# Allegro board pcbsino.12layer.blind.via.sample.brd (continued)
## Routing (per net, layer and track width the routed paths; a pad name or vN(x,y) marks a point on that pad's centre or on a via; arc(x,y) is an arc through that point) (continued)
DDR1_D9: length 19.7
  TOP w0.114: U6.AF27 19.85,38.39 19.19,38.39 18.44,37.63 18,37.63 17.82,37.81 17.82,38.09 17.97,38.24 v2(18.48,38.24) ; v2(15.51,41.36) 15.64,41.24 16.53,41.24 16.78,41.49 16.78,42.41 16.88,42.51 17.04,42.51 17.14,42.61 17.14,42.75 17.04,42.85 16.88,42.85 16.78,42.95 16.78,43.09 16.88,43.19 17.04,43.19 17.14,43.29 17.14,43.44 17.04,43.54 16.88,43.54 16.78,43.64 16.78,44.1 16.67,44.21 U8.A7
  INT_L3 w0.091: v2(15.51,41.36) 15.51,43.33 15.6,43.42 15.83,43.42 15.92,43.33 15.92,40.86 17.6,39.17 17.6,39.06 17.44,38.89 17.44,38.78 17.52,38.7 17.63,38.7 17.8,38.86 17.91,38.86 17.99,38.78 17.99,38.67 17.82,38.51 17.82,38.39 17.9,38.31 18.02,38.31 18.18,38.47 18.3,38.47 18.48,38.29 v2(18.48,38.24)
DDR1_D10: length 19.7
  TOP w0.114: v2(13.86,47.82) 14.25,48.21 U8.C2 ; U6.AG27 20.26,38.77 v2(19.93,39.1)
  INT_L3 w0.091: v2(13.86,47.82) 13.83,47.79 13.83,47.48 13.93,47.38 14.08,47.38 14.16,47.46 14.16,48.17 14.24,48.25 14.39,48.25 14.47,48.17 14.47,47.46 14.55,47.38 14.72,47.38 14.8,47.46 14.8,48.73 14.88,48.81 15.05,48.81 15.13,48.73 15.13,47.46 15.21,47.38 15.91,47.38 15.99,47.46 15.99,48.14 16.07,48.22 16.18,48.22 16.26,48.14 16.26,47.46 16.34,47.38 16.81,47.38 17.74,46.45 17.74,41.41 17.75,41.41 17.75,41.4 19.93,39.21 v2(19.93,39.1)
DDR1_D11: length 19.7
  TOP w0.114: v2(15.54,43.83) 15.13,43.42 U8.B8 ; U6.AF28 19.31,37.97 18.61,37.27 17.59,37.27 17.09,37.78 17.09,38.33 17.19,38.43 17.7,38.43 17.8,38.53 17.8,38.67 17.7,38.77 17.19,38.77 17.09,38.87 v2(17.09,39.21)
  INT_L3 w0.091: v2(17.09,39.21) 16.98,39.31 16.67,39.31 16.52,39.46 16.52,39.57 16.62,39.68 16.62,39.79 16.54,39.87 16.43,39.87 16.32,39.77 16.21,39.77 16.13,39.85 16.13,39.96 16.23,40.07 16.23,40.18 16.15,40.26 16.04,40.26 15.93,40.16 15.82,40.16 15.74,40.24 15.74,40.35 15.84,40.45 15.84,40.57 15.76,40.65 15.65,40.65 15.55,40.54 15.43,40.54 15.35,40.62 15.35,40.74 15.46,40.84 15.46,40.96 15.38,41.04 15.26,41.04 15.16,40.93 15.04,40.93 14.96,41.01 14.96,41.13 15.07,41.23 15.07,41.34 14.99,41.42 14.87,41.42 14.77,41.32 14.66,41.32 14.58,41.4 14.58,41.51 14.68,41.62 14.68,41.73 14.6,41.81 14.49,41.81 14.38,41.71 14.27,41.71 14.11,41.86 14.11,42.01 14.3,42.19 15.11,42.19 15.21,42.29 15.21,42.42 15.11,42.51 14.21,42.51 14.11,42.6 14.11,42.77 14.19,42.85 15.13,42.85 15.21,42.93 15.21,43.04 15.13,43.12 14.19,43.12 14.11,43.2 14.11,43.35 14.22,43.45 15.16,43.45 v2(15.54,43.83)
DDR1_D12: length 19.7
  TOP w0.114: U6.AE26 20.74,37.5 v2(20.74,37.53) ; v2(13.73,46.7) 13.73,46.81 U8.C3
  INT_L3 w0.091: v2(20.74,37.53) 20.74,37.63 19.55,38.82 19.55,39.23 17.44,41.34 17.44,46.01 16.91,46.55 16.67,46.55 16.59,46.63 16.59,47 16.51,47.08 16.4,47.08 16.32,47 16.32,46.63 16.24,46.55 16.12,46.55 16.04,46.63 16.04,47 15.96,47.08 15.85,47.08 15.77,47 15.77,46.63 15.69,46.55 15.57,46.55 15.49,46.63 15.49,47 15.41,47.08 15.3,47.08 15.22,47 15.22,46.63 15.14,46.55 15.02,46.55 14.94,46.63 14.94,47 14.86,47.08 14.75,47.08 14.67,47 14.67,46.63 14.59,46.55 14.48,46.55 14.4,46.63 14.4,47 14.31,47.08 14.2,47.08 14.12,47 14.12,46.63 14.04,46.55 13.82,46.55 13.73,46.64 v2(13.73,46.7)
DDR1_D13: length 19.7
  TOP w0.114: U6.AC25 21.87,35.65 v2(21.53,35.98) ; v2(13.07,45.89) 12.3,45.89 12.18,45.77 12.18,44.88 12.3,44.77 13.41,44.77 13.53,44.65 U8.D7
  INT_L3 w0.091: v2(21.53,35.98) 21.53,36.06 20.93,36.67 19.45,36.67 19.12,37 18.33,37 16.76,38.57 16.37,38.57 13.5,41.44 13.5,43.24 13,43.75 13,44.12 13.08,44.2 13.12,44.2 13.2,44.28 13.2,44.39 13.12,44.47 13.08,44.47 13,44.55 13,44.66 13.08,44.75 13.12,44.75 13.2,44.83 13.2,44.94 13.12,45.02 13.08,45.02 13,45.1 13,45.81 v2(13.07,45.89)
DDR1_D14: length 19.7
  TOP w0.114: U8.C8 13.92,43.82 13.92,44.93 14.04,45.05 14.57,45.05 14.65,45.13 14.65,45.57 14.53,45.68 13.66,45.68 v2(13.4,45.43) ; U6.AC24 22.67,35.68 v2(22.29,36.06)
  INT_L3 w0.091: v2(22.29,36.06) 21.91,36.06 21,36.97 19.55,36.97 19.09,37.43 18.38,37.43 16.91,38.9 16.53,38.9 13.81,41.62 13.81,43.5 13.48,43.83 13.48,45.35 v2(13.4,45.43)
DDR1_D15: length 19.7
  TOP w0.114: v2(22.24,36.77) 21.87,36.39 U6.AD25 ; U8.A3 v2(16.7,48.18)
  INT_L3 w0.091: v2(22.24,36.77) 22.24,36.92 21.81,37.35 21.45,37.35 21.33,37.47 21.33,37.59 21.44,37.69 21.44,37.8 21.36,37.88 21.24,37.88 21.14,37.78 21.03,37.78 20.8,38.01 20.8,38.12 20.9,38.23 20.9,38.34 20.82,38.42 20.7,38.42 20.6,38.32 20.49,38.32 20.39,38.42 20.39,39.13 18,41.52 18,41.79 18.08,41.87 18.48,41.87 18.56,41.95 18.56,42.06 18.48,42.14 18.08,42.14 18,42.22 18,42.48 18.08,42.56 18.12,42.56 18.2,42.64 18.2,42.76 18.12,42.84 18.08,42.84 18,42.92 18,43.03 18.08,43.11 18.12,43.11 18.2,43.19 18.2,43.31 18.12,43.39 18.08,43.39 18,43.47 18,43.58 18.08,43.66 18.12,43.66 18.2,43.74 18.2,43.86 18.12,43.94 18.08,43.94 18,44.02 18,44.13 18.08,44.21 18.12,44.21 18.2,44.29 18.2,44.4 18.12,44.48 18.08,44.48 18,44.56 18,44.68 18.08,44.76 18.12,44.76 18.2,44.84 18.2,44.95 18.12,45.03 18.08,45.03 18,45.11 18,45.23 18.08,45.31 18.12,45.31 18.2,45.39 18.2,45.5 18.12,45.58 18.08,45.58 18,45.66 18,45.78 18.08,45.86 18.12,45.86 18.2,45.94 18.2,46.05 18.12,46.13 18.08,46.13 18,46.21 18,46.32 18.08,46.4 18.12,46.4 18.2,46.48 18.2,46.6 18.12,46.68 18.08,46.68 18,46.76 18,46.98 17.63,47.35 17.52,47.35 17.45,47.28 17.34,47.28 17.26,47.36 17.26,47.48 17.32,47.54 17.32,47.66 17.24,47.74 17.13,47.74 17.06,47.67 16.95,47.67 16.87,47.75 16.87,47.87 16.93,47.93 16.93,48.04 16.8,48.18 v2(16.7,48.18)
DDR1_D16: length 17.4
  TOP w0.114: v8(12.33,31.81) 11.93,32.21 U9.F8
  TOP w0.12: v8(25.47,31.97) U6.V20
  SIG_L5 w0.091: v8(12.33,31.81) 12.33,31.72 12.64,31.41 14.31,31.41 14.39,31.49 14.39,31.86 14.47,31.94 14.58,31.94 14.66,31.86 14.66,31.49 14.74,31.41 14.85,31.41 14.93,31.49 14.93,31.86 15.01,31.94 15.13,31.94 15.21,31.86 15.21,31.49 15.29,31.41 15.4,31.41 15.48,31.49 15.48,31.86 15.56,31.94 15.68,31.94 15.76,31.86 15.76,31.49 15.84,31.41 16.88,31.41 17.06,31.59 25.21,31.59 25.47,31.84 v8(25.47,31.97)
DDR1_D17: length 17.4
  TOP w0.12: U9.H8 v8(10.73,31.81) ; v8(25.47,32.77) U6.W20
  SIG_L5 w0.091: v8(25.47,32.77) 25.07,32.37 23.93,32.37 23.84,32.29 23.84,32.18 23.76,32.09 23.12,32.09 22.99,32.22 22.83,32.22 22.7,32.09 22.53,32.09 22.41,32.22 22.24,32.22 22.11,32.09 21.94,32.09 21.82,32.22 21.65,32.22 21.52,32.09 21.35,32.09 21.23,32.22 21.06,32.22 20.93,32.09 20.76,32.09 20.64,32.22 20.47,32.22 20.34,32.09 20.18,32.09 20.05,32.22 19.88,32.22 19.75,32.09 18.99,32.09 18.41,32.68 13.12,32.68 12.67,32.22 11.14,32.22 v8(10.73,31.81)
DDR1_D18: length 17.5
  TOP w0.114: v8(12.88,35.72) 12.89,35.73 12.89,36.04 U9.E3 ; U6.AB28 18.09,34.77 17.64,35.22 17.64,35.67 v8(17.62,35.7)
  SIG_L5 w0.091: v8(17.62,35.7) 17.62,36.67 17.53,36.75 17.05,36.75 16.96,36.84 16.96,36.96 17.05,37.05 17.53,37.05 17.62,37.13 17.62,37.96 17.49,38.09 17.18,38.09 17.09,38 17.09,37.66 16.73,37.3 16.11,37.3 15.66,36.86 15.66,36.84 14.87,36.84 14.69,37.03 14.69,37.44 14.6,37.53 14.48,37.53 14.39,37.44 14.39,37.03 14.31,36.94 13.99,36.94 13.9,36.86 13.9,36.68 13.82,36.59 13.7,36.59 13.61,36.68 13.61,36.86 13.52,36.94 13.23,36.94 12.82,36.54 11.32,36.54 11.24,36.46 11.24,36.2 11.34,36.11 12.59,36.11 12.88,35.82 v8(12.88,35.72)
DDR1_D19: length 17.5
  TOP w0.114: U9.F2 11.93,37.01 v8(12.33,37.41)
  TOP w0.12: U6.AC28 18.99,35.57 v8(18.88,35.69)
  SIG_L5 w0.091: v8(12.33,37.41) 11.93,37.81 10.17,37.81 10.02,37.95 10.02,38.62 10.2,38.8 17.77,38.8 18.88,37.69 18.88,37.09 18.96,37.01 19.31,37.01 19.4,36.92 19.4,36.8 19.31,36.71 18.96,36.71 18.88,36.63 18.88,36.5 18.96,36.42 19.31,36.42 19.4,36.33 19.4,36.21 19.31,36.12 18.96,36.12 18.88,36.04 v8(18.88,35.69)
DDR1_D20: length 17.4
  TOP w0.12: v8(10.73,36.61) 10.33,36.21 U9.H3 ; v8(19.87,35.97) U6.AC27
  SIG_L5 w0.091: v8(10.73,36.61) 10.28,36.16 9.54,36.16 9.21,35.83 9.21,34.07 9.69,33.59 11.37,33.59 12.11,34.33 19.45,34.33 20.06,34.94 20.06,35.78 v8(19.87,35.97)
DDR1_D21: length 17.4
  TOP w0.114: v8(10.73,32.61) U9.H7
  TOP w0.12: v8(26.27,33.57) U6.Y19
  SIG_L5 w0.091: v8(10.73,32.61) 11.18,33.06 12.18,33.06 12.67,33.54 20.31,33.54 20.77,34 25.62,34 25.63,34 25.84,34 v8(26.27,33.57)
DDR1_D22: length 17.5
  TOP w0.114: v8(11.53,37.41) 11.13,37.01 U9.G2
  TOP w0.12: v8(18.23,35.7) 18.23,35.29 18.35,35.17 19.87,35.17 U6.AB27
  SIG_L5 w0.091: v8(11.53,37.41) 11.45,37.33 11.45,37.03 11.54,36.94 12.61,36.94 12.75,37.08 12.75,37.69 12.89,37.83 13.73,37.83 13.82,37.92 13.82,38.36 13.9,38.44 14.03,38.44 14.11,38.36 14.11,37.92 14.2,37.83 15.69,37.83 16.32,38.47 17.67,38.47 18.08,38.06 18.08,37.85 18.19,37.75 18.39,37.75 18.56,37.58 18.56,37.18 18.47,37.09 18.01,37.09 17.92,37 17.92,36.88 18.01,36.8 18.47,36.8 18.56,36.71 18.56,36.59 18.47,36.5 18.01,36.5 17.92,36.41 17.92,36.29 18.01,36.21 18.47,36.21 18.56,36.12 18.56,35.93 18.33,35.7 v8(18.23,35.7)
DDR1_D23: length 17.4
  TOP w0.114: v8(12.33,32.61) U9.F7
  TOP w0.12: U6.Y20 v8(25.47,33.57)
  SIG_L5 w0.091: v8(25.47,33.57) 25.47,33.41 25.24,33.19 24.99,33.19 24.9,33.28 24.9,33.42 24.8,33.52 24.62,33.52 24.53,33.42 24.53,33.28 24.44,33.19 24.26,33.19 24.16,33.28 24.16,33.42 24.07,33.52 23.89,33.52 23.8,33.42 23.8,33.28 23.71,33.19 23.52,33.19 23.43,33.28 23.43,33.42 23.34,33.52 23.16,33.52 23.07,33.42 23.07,33.28 22.98,33.19 22.79,33.19 22.7,33.28 22.7,33.42 22.61,33.52 22.43,33.52 22.34,33.42 22.34,33.28 22.24,33.19 22.06,33.19 21.97,33.28 21.97,33.42 21.88,33.52 21.7,33.52 21.6,33.42 21.6,33.28 21.51,33.19 21.33,33.19 21.24,33.28 21.24,33.42 21.15,33.52 20.96,33.52 20.87,33.42 20.87,33.28 20.78,33.19 12.91,33.19 v8(12.33,32.61)
DDR1_D24: length 10.3
  TOP w0.114: U9.A2 16.34,37.01 16.47,37.14 v2(16.48,37.14)
  TOP w0.12: v2(23.83,34.34) U6.AA23
  INT_L3 w0.091: v2(16.48,37.14) 17.07,37.14 17.18,37.02 17.18,36.9 17.01,36.73 17.01,36.61 17.1,36.52 17.22,36.52 17.39,36.69 17.51,36.69 18.03,36.18 18.97,36.18 19.55,35.6 19.71,35.6 19.71,35.6 20.69,35.6 21.12,35.17 21.73,35.17 22.14,34.76 23.49,34.76 23.83,34.41 v2(23.83,34.34)
DDR1_D25: length 10.3
  TOP w0.114: v2(15.39,31.83) 15.33,31.89 15.13,32.19 U9.B8
  TOP w0.12: v2(23.87,32.78) U6.Y22
  INT_L3 w0.091: v2(15.39,31.83) 15.75,31.83 16.12,32.19 16.53,32.19 16.88,31.84 23.16,31.84 23.87,32.55 v2(23.87,32.78)
DDR1_D26: length 10.3
  TOP w0.114: U9.C8 v2(14.67,31.86)
  TOP w0.12: v2(23.14,32.85) U6.Y23
  INT_L3 w0.091: v2(23.14,32.85) 22.39,32.1 18.63,32.1 18.03,32.7 16.17,32.7 15.66,32.19 15,32.19 v2(14.67,31.86)
DDR1_D27: length 10.3
  TOP w0.114: U9.A3 15.52,36.61 v2(15.51,36.61)
  TOP w0.12: U6.AA24 23,34.3 v2(23.05,34.3)
  INT_L3 w0.091: v2(15.51,36.61) 15.59,36.69 15.88,36.69 16.07,36.5 16.07,35.5 16.27,35.29 20.56,35.29 20.97,34.89 21.61,34.89 22.01,34.48 22.96,34.48 23.05,34.39 v2(23.05,34.3)
DDR1_D28: length 10.3
  TOP w0.114: U9.A7 15.91,33.01 v2(15.53,32.63)
  TOP w0.12: U6.Y24 22.99,33.49 v2(23,33.49)
  INT_L3 w0.091: v2(15.53,32.63) 15.49,32.67 15.49,32.89 15.58,32.98 18.28,32.98 18.91,32.35 20.82,32.35 20.95,32.48 20.95,33.16 21.23,33.44 21.65,33.44 21.73,33.35 21.73,33.27 21.82,33.19 21.94,33.19 22.03,33.27 22.03,33.35 22.11,33.44 22.95,33.44 v2(23,33.49)
DDR1_D29: length 10.3
  TOP w0.114: U9.C2 v2(14.69,37.36)
  TOP w0.12: U6.AA26 21.02,33.97 v2(20.6,34.39)
  INT_L3 w0.091: v2(14.69,37.36) 14.14,36.82 14.14,36.63 14.23,36.54 14.36,36.54 14.44,36.45 14.44,36.33 14.36,36.24 14.28,36.24 14.19,36.16 14.19,35.75 15.21,34.73 20.26,34.73 v2(20.6,34.39)
DDR1_D30: length 10.3
  TOP w0.114: U9.C3 14.71,36.59 v2(14.75,36.59)
  TOP w0.12: v2(21.53,34.31) U6.AA25
  INT_L3 w0.091: v2(21.53,34.31) 21.31,34.53 20.96,34.53 20.48,35.01 15.99,35.01 15.83,35.17 15.69,35.17 15.54,35.01 15.33,35.01 15.19,35.16 15.19,35.28 15.2,35.3 15.2,35.42 15.12,35.51 15,35.51 14.98,35.49 14.86,35.49 14.75,35.6 14.75,35.87 14.84,35.96 15.07,35.96 15.16,36.05 15.16,36.17 15.07,36.25 14.84,36.25 14.75,36.34 v2(14.75,36.59)
DDR1_D31: length 10.3
  TOP w0.114: U6.AA28 19.37,34.07 v2(19.04,34.07) ; U9.D7 13.53,32.93 v2(13.17,32.58)
  INT_L3 w0.091: v2(13.17,32.58) 12.69,33.06 12.69,34.79 12.95,35.04 13.68,35.04 14.57,34.15 18.81,34.15 18.89,34.07 v2(19.04,34.07)
DDR1_DQM0: length 20.9
  TOP w0.114: v8(12.33,43.81) U8.E7
  TOP w0.12: v8(23.07,36.77) U6.AD23
  SIG_L5 w0.091: v8(12.33,43.81) 11.93,43.41 11.93,41.97 12.34,41.57 13.46,41.57 13.55,41.66 13.55,41.93 13.64,42.02 13.82,42.02 13.91,41.93 13.91,41.66 14,41.57 14.19,41.57 14.28,41.66 14.28,42.06 14.41,42.19 15.5,42.19 16.12,41.57 16.79,41.57 16.88,41.66 16.88,42.62 16.98,42.71 17.16,42.71 17.25,42.62 17.25,41.66 17.34,41.57 17.64,41.57 18.33,40.88 18.89,40.88 21.05,38.72 21.7,38.72 21.78,38.8 22.11,38.8 22.11,38.8 22.47,38.8 22.7,38.57 22.7,37.74 22.69,37.73 22.69,37.15 v8(23.07,36.77)
DDR1_DQM1: length 19.7
  TOP w0.114: U8.D3 13.53,47.18 v2(13.02,46.67) ; U6.AB23 v2(23.06,35.18)
  INT_L3 w0.091: v2(13.02,46.67) 12.72,46.37 12.72,41.82 16.3,38.24 16.65,38.24 18.31,36.59 19.07,36.59 19.24,36.41 20.82,36.41 21.12,36.11 21.12,35.9 21.43,35.6 22.64,35.6 v2(23.06,35.18)
DDR1_DQM2: length 17.4
  TOP w0.114: U9.E7 12.18,33.55 v8(12.18,33.77)
  TOP w0.12: v8(20.67,35.97) U6.AC26
  SIG_L5 w0.091: v8(20.67,35.97) 20.75,36.06 21.74,36.06 21.84,35.96 21.84,35.82 21.75,35.74 21.16,35.74 21.07,35.65 21.07,35.53 21.16,35.44 21.75,35.44 21.84,35.35 21.84,35.23 21.75,35.15 20.86,35.15 20.77,35.06 20.77,34.94 20.86,34.85 21.75,34.85 21.84,34.77 21.84,34.53 21.68,34.38 20.51,34.38 19.98,33.85 12.34,33.85 12.26,33.77 v8(12.18,33.77)
DDR1_DQM3: length 10.3
  TOP w0.114: U9.D3 13.17,36.56 v2(13.12,36.56)
  TOP w0.12: v2(19.99,34.26) U6.AA27
  INT_L3 w0.091: v2(19.99,34.26) 19.81,34.43 14.7,34.43 14.4,34.73 14.4,34.85 14.5,34.95 14.5,35.07 14.42,35.16 14.3,35.16 14.19,35.06 14.07,35.06 13.98,35.14 13.98,35.27 14.09,35.37 14.09,35.49 14,35.58 13.88,35.58 13.78,35.47 13.65,35.47 13.5,35.62 13.5,36.6 13.41,36.69 13.25,36.69 v2(13.12,36.56)
DDR1_DQS0_N: length 21
  TOP w0.102: v8(11.53,47.81) 11.49,47.81 11.13,47.45 U8.G3 ; U6.AG25 21.55,39.09 21.55,39.13 v8(21.49,39.18)
  SIG_L5 w0.089: v8(11.53,47.81) 11.78,47.56 11.78,46.33 12.24,45.87 12.84,45.87 12.93,45.78 12.93,45.56 13.16,45.33 13.54,45.33 13.77,45.56 13.77,45.78 13.86,45.87 14.03,45.87 14.12,45.78 14.12,45.56 14.35,45.33 14.73,45.33 14.96,45.56 14.96,45.78 15.05,45.87 15.23,45.87 15.32,45.78 15.32,45.56 15.55,45.33 15.92,45.33 16.15,45.56 16.15,45.78 16.24,45.87 16.42,45.87 16.51,45.78 16.51,45.56 16.74,45.33 17.12,45.33 17.35,45.56 17.35,45.78 17.44,45.87 18.37,45.87 21.33,42.91 21.33,40.91 20.74,40.32 20.74,39.74 21.12,39.36 21.4,39.36 21.49,39.27 v8(21.49,39.18)
DDR1_DQS0_P: length 21
  TOP w0.102: U8.F3 11.93,47.46 12.26,47.79 12.31,47.79 v8(12.33,47.81) ; v8(21.49,39.98) 21.5,39.97 21.5,39.94 U6.AH25
  SIG_L5 w0.089: v8(12.33,47.81) 12.29,47.81 12.29,47.82 12.11,47.82 12.02,47.73 12.02,46.43 12.34,46.11 12.94,46.11 13.17,45.88 13.17,45.66 13.26,45.57 13.44,45.57 13.53,45.66 13.53,45.88 13.76,46.11 14.13,46.11 14.36,45.88 14.36,45.66 14.45,45.57 14.63,45.57 14.72,45.66 14.72,45.88 14.95,46.11 15.33,46.11 15.56,45.88 15.56,45.66 15.65,45.57 15.82,45.57 15.91,45.66 15.91,45.88 16.14,46.11 16.52,46.11 16.75,45.88 16.75,45.66 16.84,45.57 17.02,45.57 17.11,45.66 17.11,45.88 17.34,46.11 18.47,46.11 21.57,43.01 21.57,40.81 20.98,40.22 20.98,39.84 21.22,39.6 21.39,39.6 21.51,39.71 21.51,39.97 v8(21.49,39.98)
DDR1_DQS1_N: length 19.8
  TOP w0.102: U6.AE28 19.47,37.32 19.63,37.48 v2(19.63,37.53) ; v2(14.7,43.75) 15.13,44.18 U8.B7
  INT_L3 w0.089: v2(14.7,43.75) 14.91,43.97 14.91,44.66 14.68,44.89 14.16,44.89 14.08,44.98 14.08,45.8 14.24,45.96 15.03,45.96 15.31,45.68 15.31,44.87 15.53,44.65 15.9,44.65 16.15,44.89 16.15,45.65 16.23,45.74 16.62,45.74 16.74,45.57 16.74,44.51 16.66,44.44 16.52,44.44 16.3,44.22 16.3,43.91 16.52,43.69 16.66,43.69 16.74,43.61 16.74,41.84 16.66,41.76 16.49,41.76 16.27,41.54 16.27,41.23 16.49,41.01 16.66,41.01 16.74,40.93 16.74,40.55 17.17,40.13 17.48,40.13 17.65,40.3 17.76,40.3 17.83,40.22 17.83,40.11 17.66,39.94 17.66,39.63 18.74,38.56 18.87,38.56 19.65,37.78 19.65,37.55 v2(19.63,37.53)
DDR1_DQS1_P: length 19.7
  TOP w0.102: U8.C7 14.37,44.17 v2(14.4,44.17) ; v2(20.19,37.53) 20.27,37.46 U6.AE27
  INT_L3 w0.089: v2(14.4,44.17) 14.67,44.44 14.67,44.56 14.58,44.65 14.06,44.65 13.83,44.88 13.83,45.9 14.14,46.2 15.13,46.2 15.55,45.78 15.55,44.97 15.63,44.89 15.8,44.89 15.9,44.99 15.9,45.75 16.14,45.98 16.75,45.98 16.98,45.65 16.98,44.41 16.76,44.19 16.62,44.19 16.54,44.12 16.54,44.01 16.62,43.93 16.76,43.93 16.98,43.71 16.98,41.74 16.76,41.52 16.59,41.52 16.51,41.44 16.51,41.33 16.59,41.25 16.76,41.25 16.98,41.03 16.98,40.65 17.26,40.37 17.38,40.37 17.55,40.54 17.86,40.54 18.08,40.32 18.08,40.01 17.91,39.84 17.91,39.73 18.84,38.8 18.97,38.8 20.12,37.64 20.12,37.6 v2(20.19,37.53)
DDR1_DQS2_N: length 17.5
  TOP w0.102: v8(11.09,35.6) 11.29,35.8 11.29,36.04 U9.G3 ; v8(16.88,35.67) 16.88,35.88 17.52,36.51 19.33,36.51 U6.AD28
  SIG_L5 w0.089: v8(16.88,35.67) 16.74,35.81 16.07,35.81 15.74,36.15 15.41,36.15 15.19,35.93 15.19,35.15 14.91,34.87 14.33,34.87 14.11,35.1 14.11,35.76 14.02,35.84 13.9,35.84 13.82,35.76 13.82,35.1 13.59,34.87 12.17,34.87 11.45,34.15 9.9,34.15 9.67,34.38 9.67,35.14 9.9,35.37 10.58,35.37 10.82,35.13 11.17,35.13 11.37,35.33 11.37,35.47 11.24,35.6 v8(11.09,35.6)
DDR1_DQS2_P: length 17.5
  TOP w0.102: v8(11.73,35.6) 11.73,36.01 U9.F3 ; U6.AD27 19.87,36.77 17.37,36.77 16.81,36.21 v8(16.6,36.21)
  SIG_L5 w0.089: v8(16.6,36.21) 16.5,36.11 16.12,36.11 15.84,36.39 15.31,36.39 14.95,36.03 14.95,35.25 14.81,35.12 14.43,35.12 14.35,35.2 14.35,35.86 14.12,36.09 13.8,36.09 13.57,35.86 13.57,35.2 13.49,35.12 12.07,35.12 11.35,34.39 10,34.39 9.91,34.48 9.91,35.04 10,35.13 10.48,35.13 10.72,34.89 11.27,34.89 11.61,35.23 11.61,35.48 v8(11.73,35.6)
DDR1_DQS3_N: length 10.3
  TOP w0.102: v2(20.54,33.46) 20.54,33.46 20.27,33.19 U6.Y27 ; v2(14.77,32.68) 14.78,32.68 14.8,32.68 U9.B7
  INT_L3 w0.089: v2(20.54,33.46) 20.3,33.22 18.72,33.22 18.42,33.52 14.36,33.52 13.94,33.93 13.63,33.93 13.49,33.8 13.49,33.51 13.83,33.17 14.29,33.17 14.77,32.69 v2(14.77,32.68)
DDR1_DQS3_P: length 10.4
  TOP w0.102: U6.Y28 19.54,33.17 v2(19.88,33.52) ; v2(14,32.61) 14.06,32.61 14.33,32.96 U9.C7
  INT_L3 w0.089: v2(14,32.61) 14.17,32.61 14.28,32.72 14.28,32.84 14.19,32.93 13.73,32.93 13.25,33.41 13.25,33.9 13.53,34.18 14.04,34.18 14.46,33.76 18.52,33.76 18.82,33.46 19.82,33.46 v2(19.88,33.52)
DDR1_ODT0: length 54.7
  TOP w0.114: U8.K1 v8(9.14,49.42) ; U6.AE20 25.87,37.2 v8(25.49,37.58)
  TOP w0.12: U9.K1 v8(8.33,38.21)
  INT_L3 w0.094: v8(9.14,49.42) 8.73,49.01 8.73,47.11 9.87,45.96 9.87,41.01 8.33,39.46 v8(8.33,38.21)
  SIG_L8 w0.091: v8(9.14,49.42) 9.14,50.37 9.23,50.46 9.54,50.46 9.63,50.37 9.63,49.96 9.72,49.87 9.86,49.87 9.95,49.96 9.95,50.37 10.04,50.46 10.18,50.46 10.27,50.37 10.27,49.96 10.36,49.87 10.5,49.87 10.59,49.96 10.59,50.37 10.68,50.46 10.82,50.46 10.91,50.37 10.91,49.96 11,49.87 11.14,49.87 11.23,49.96 11.23,50.37 11.32,50.46 11.46,50.46 11.55,50.37 11.55,49.96 11.64,49.87 11.78,49.87 11.87,49.96 11.87,50.37 11.96,50.46 12.1,50.46 12.19,50.37 12.19,49.96 12.28,49.87 12.42,49.87 12.51,49.96 12.51,50.37 12.6,50.46 12.74,50.46 12.83,50.37 12.83,49.96 12.92,49.87 13.06,49.87 13.15,49.96 13.15,50.37 13.24,50.46 13.38,50.46 13.47,50.37 13.47,49.96 13.56,49.87 13.7,49.87 13.79,49.96 13.79,50.37 13.88,50.46 14.02,50.46 14.11,50.37 14.11,49.96 14.2,49.87 14.34,49.87 14.43,49.96 14.43,50.37 14.52,50.46 14.66,50.46 14.75,50.37 14.75,49.96 14.84,49.87 14.98,49.87 15.07,49.96 15.07,50.37 15.16,50.46 15.3,50.46 15.39,50.37 15.39,49.96 15.48,49.87 15.62,49.87 15.71,49.96 15.71,50.37 15.8,50.46 15.94,50.46 16.03,50.37 16.03,49.96 16.12,49.87 16.26,49.87 16.35,49.96 16.35,50.37 16.44,50.46 16.58,50.46 16.67,50.37 16.67,49.96 16.76,49.87 16.9,49.87 16.99,49.96 16.99,50.37 17.08,50.46 17.22,50.46 17.31,50.37 17.31,49.96 17.4,49.87 17.54,49.87 17.63,49.96 17.63,50.37 17.72,50.46 18.51,50.46 18.76,50.2 18.76,49.98 18.67,49.89 18.17,49.89 18.08,49.8 18.08,49.66 18.17,49.57 18.67,49.57 18.76,49.48 18.76,46.9 25.07,40.59 25.07,37.99 25.48,37.58 v8(25.49,37.58)
  BOTTOM w0.114: 8.33,38.81 8.48,38.96 R92.2
  BOTTOM w0.12: 8.33,38.81 v8(8.33,38.21)
DDR1_RASN: length 54.8
  TOP w0.12: v8(9.13,36.61) U9.J3 ; v8(26.27,37.57) U6.AF20 ; U8.J3 v8(9.13,47.81)
  INT_L3 w0.094: v8(9.13,36.61) 8.75,36.99 8.75,39.28 10.23,40.75 10.23,46.19 9.13,47.29 v8(9.13,47.81)
  SIG_L5 w0.091: v8(26.27,37.57) 25.9,37.94 25.9,39.07 25.81,39.16 24.92,39.16 24.83,39.26 24.83,39.39 24.92,39.48 25.81,39.48 25.9,39.58 25.9,39.71 25.81,39.8 24.92,39.8 24.83,39.9 24.83,40.03 24.92,40.12 25.81,40.12 25.9,40.22 25.9,40.35 25.81,40.44 24.92,40.44 24.83,40.54 24.83,40.67 24.92,40.76 25.81,40.76 25.9,40.86 25.9,40.99 25.81,41.08 24.92,41.08 24.83,41.18 24.83,41.31 24.92,41.4 25.81,41.4 25.9,41.5 25.9,41.63 25.81,41.72 24.92,41.72 24.83,41.82 24.83,41.95 24.92,42.04 25.81,42.04 25.9,42.14 25.9,43.45 21.31,48.04 20.21,48.04 19.77,48.48 19.77,48.61 19.99,48.82 19.99,48.95 19.89,49.05 19.76,49.05 19.55,48.84 19.42,48.84 19.32,48.93 19.32,49.06 19.53,49.28 19.53,49.41 19.44,49.5 19.31,49.5 19.09,49.29 18.97,49.29 18.87,49.39 18.87,49.52 19.08,49.73 19.08,49.86 18.98,49.96 18.86,49.96 18.64,49.74 18.51,49.74 18.28,49.97 8.96,49.97 8.73,49.75 8.73,48.21 v8(9.13,47.81)
  BOTTOM w0.114: R70.2 9.19,35.95 9.13,36.01
  BOTTOM w0.12: 9.13,36.01 v8(9.13,36.61)
DDR1_RST: length 55.7
  TOP w0.114: U6.AG21 v2(25.42,39.13)
  TOP w0.12: U8.T2 3.93,48.21 3.51,48.63 v8(2.94,48.63) ; U9.T2 3.93,37.01 v8(3.53,37.41)
  INT_L3 w0.091: v8(2.94,48.63) 2.94,51.19 4.49,52.74 17.92,52.74 21.28,49.39 21.28,45.33 27.47,39.13 27.47,38.11 27.35,37.99 26.15,37.99 25.9,38.24 25.9,38.65 25.58,38.96 ; 25.39,39.1 25.44,39.1 25.58,38.96 ; v2(25.42,39.13) 25.58,38.96
  SIG_L5 w0.091: v8(2.94,48.63) 2.3,47.99 2.3,38.77 2.48,38.6 2.48,38.46 v8(3.53,37.41)
  BOTTOM w0.114: v8(3.53,37.41) 3.53,38.7 R95.1
DDR1_WEN: length 54.7
  TOP w0.114: U8.L3 v2(7.52,47.82) ; U6.AH21 25.07,39.73 24.17,40.63 22.52,40.63 v2(22.17,40.98)
  TOP w0.12: v8(7.53,36.61) 7.93,36.21 U9.L3
  INT_L3 w0.091: v2(22.17,40.98) 22.17,41.26 21.77,41.66 21.64,41.66 21.42,41.43 21.29,41.43 21.19,41.53 21.19,41.66 21.42,41.88 21.42,42.01 21.32,42.11 21.19,42.11 20.96,41.88 20.84,41.88 20.74,41.98 20.74,42.11 20.96,42.33 20.96,42.46 20.87,42.56 20.74,42.56 20.51,42.33 20.38,42.33 20.29,42.43 20.29,42.56 20.51,42.79 20.51,42.92 20.42,43.01 20.29,43.01 20.06,42.79 19.93,42.79 19.83,42.88 19.83,43.01 20.06,43.24 20.06,43.37 19.96,43.47 19.83,43.47 19.61,43.24 19.48,43.24 19.38,43.34 19.38,43.47 19.61,43.69 19.61,43.82 19.33,44.1 19.33,48.78 17.75,50.36 17.36,50.36 17.27,50.26 17.27,50.02 17.18,49.92 17.04,49.92 16.95,50.02 16.95,50.26 16.86,50.36 16.72,50.36 16.63,50.26 16.63,50.02 16.54,49.92 16.4,49.92 16.31,50.02 16.31,50.26 16.22,50.36 16.08,50.36 15.99,50.26 15.99,50.02 15.9,49.92 15.76,49.92 15.67,50.02 15.67,50.26 15.58,50.36 15.44,50.36 15.35,50.26 15.35,50.02 15.26,49.92 15.12,49.92 15.03,50.02 15.03,50.26 14.94,50.36 14.8,50.36 14.71,50.26 14.71,50.02 14.62,49.92 14.48,49.92 14.39,50.02 14.39,50.26 14.3,50.36 14.16,50.36 14.07,50.26 14.07,50.02 13.98,49.92 13.84,49.92 13.75,50.02 13.75,50.26 13.66,50.36 13.52,50.36 13.43,50.26 13.43,50.02 13.34,49.92 13.2,49.92 13.11,50.02 13.11,50.26 13.02,50.36 12.88,50.36 12.79,50.26 12.79,50.02 12.7,49.92 12.56,49.92 12.47,50.02 12.47,50.26 12.38,50.36 12.24,50.36 12.15,50.26 12.15,50.02 12.06,49.92 11.92,49.92 11.83,50.02 11.83,50.26 11.74,50.36 11.6,50.36 11.51,50.26 11.51,50.02 11.42,49.92 11.28,49.92 11.19,50.02 11.19,50.26 11.1,50.36 10.96,50.36 10.87,50.26 10.87,50.02 10.78,49.92 10.64,49.92 10.55,50.02 10.55,50.26 10.46,50.36 10.32,50.36 10.23,50.26 10.23,50.02 10.14,49.92 10,49.92 9.91,50.02 9.91,50.26 9.82,50.36 9.68,50.36 9.59,50.26 9.59,50.02 9.5,49.92 9.36,49.92 9.27,50.02 9.27,50.26 9.18,50.36 9.04,50.36 8.95,50.26 8.95,50.02 8.86,49.92 8.72,49.92 8.63,50.02 8.63,50.26 8.54,50.36 8.02,50.36 7.92,50.25 7.92,48.22 v2(7.52,47.82)
  INT_L3 w0.094: v2(7.52,47.82) 7.52,46.74 8.73,45.53 8.73,41.19 7.13,39.59 7.13,37.01 v8(7.53,36.61)
  BOTTOM w0.114: 7.53,36.01 7.54,36 R72.2
  BOTTOM w0.12: 7.53,36.01 v8(7.53,36.61)
DDR2_A0: length 45
  TOP w0.114: v8(21.29,29.79) 21.87,29.22 U6.R25 ; U10.N3 6.23,13.91 ; v8(5.91,25.41) 5.93,25.41 U11.N3
  TOP w0.12: 6.23,13.91 v8(5.93,14.21)
  INT_L3 w0.094: v8(5.91,25.41) 5.53,25.03 5.53,14.61 v8(5.93,14.21)
  SIG_L8 w0.091: v8(5.91,25.41) 5.53,25.79 5.53,27.88 5.81,28.16 6.05,28.16 6.14,28.06 6.14,26.81 6.29,26.66 6.43,26.66 6.52,26.75 6.52,28.06 6.61,28.16 7.48,28.16 7.58,28.06 7.58,26.83 7.67,26.73 7.89,26.73 7.99,26.84 7.99,28.06 8.08,28.16 8.43,28.16 8.73,27.85 8.73,25.01 8.91,24.83 10.08,24.83 10.28,25.03 10.28,27.37 10.58,27.67 15.65,27.67 15.74,27.77 15.74,28.33 15.92,28.51 16.43,28.51 17.85,29.93 20.5,29.93 20.57,30.01 21.07,30.01 v8(21.29,29.79)
  BOTTOM w0.114: R106.2 6.04,14.1 v8(5.93,14.21)
DDR2_A1: length 44.9
  TOP w0.114: U11.P7 5.53,21.81 v8(5.13,21.41) ; U10.P7 5.53,10.61
  TOP w0.12: 5.53,10.61 v8(5.13,10.21) ; 5.53,21.81 v8(5.13,21.41) ; v8(20.67,29.57) U6.R26
  SIG_L5 w0.091: v8(20.67,29.57) 20.61,29.63 18.46,29.63 18.08,29.25 17.51,29.25 17.42,29.34 17.42,29.44 17.33,29.53 17.19,29.53 17.1,29.44 17.1,29.34 17.01,29.25 16.87,29.25 16.78,29.34 16.78,29.44 16.69,29.53 16.55,29.53 16.46,29.44 16.46,29.34 16.37,29.25 16.23,29.25 16.14,29.34 16.14,29.44 16.05,29.53 15.91,29.53 15.82,29.44 15.82,29.34 15.73,29.25 15.59,29.25 15.5,29.34 15.5,29.44 15.41,29.53 15.27,29.53 15.18,29.44 15.18,29.34 15.09,29.25 14.95,29.25 14.86,29.34 14.86,29.44 14.77,29.53 14.63,29.53 14.54,29.44 14.54,29.34 14.45,29.25 7.54,29.25 7.45,29.16 7.45,28.43 7.35,28.33 7.22,28.33 7.13,28.43 7.13,29.16 7.03,29.25 6.9,29.25 6.81,29.16 6.81,28.43 6.71,28.33 6.58,28.33 6.49,28.43 6.49,29.16 6.39,29.25 6.26,29.25 6.17,29.16 6.17,28.43 6.07,28.33 5.94,28.33 5.85,28.43 5.85,29.16 5.75,29.25 5.61,29.25 5.43,29.07 5.43,27.24 4.75,26.57 4.75,23.55 5.13,23.17 v8(5.13,21.41)
  SIG_L10 w0.094: v8(5.13,21.41) 4.73,21.01 4.73,13.81 5.18,13.36 5.18,10.26 v8(5.13,10.21)
  BOTTOM w0.12: R107.2 5.13,10.95 v8(5.13,10.21)
DDR2_A2: length 44.9
  TOP w0.114: U10.P3 5.53,13.81 ; v2(18.1,30.42) 18.1,29.73 18.66,29.17 U6.R28 ; 5.26,25.27 U11.P3 5.53,25.01
  TOP w0.12: 5.53,25.01 5.26,25.27 5.26,25.27 v2(5.12,25.41) ; 5.53,13.81 v8(5.13,14.21)
  INT_L3 w0.091: v2(18.1,30.42) 18.03,30.42 17.95,30.34 16.35,30.34 16.25,30.24 16.06,30.24 15.95,30.34 15.76,30.34 15.66,30.24 15.47,30.24 15.36,30.34 15.17,30.34 15.07,30.24 14.88,30.24 14.78,30.34 14.58,30.34 14.48,30.24 14.29,30.24 14.19,30.34 13.99,30.34 13.89,30.24 13.7,30.24 13.6,30.34 13.4,30.34 13.3,30.24 13.11,30.24 13.01,30.34 12.81,30.34 12.71,30.24 12.52,30.24 12.42,30.34 12.23,30.34 12.12,30.24 11.93,30.24 11.83,30.34 11.64,30.34 11.53,30.24 11.34,30.24 11.24,30.34 11.05,30.34 10.95,30.24 10.75,30.24 10.65,30.34 10.46,30.34 10.36,30.24 10.16,30.24 10.06,30.34 9.87,30.34 9.77,30.24 9.57,30.24 9.47,30.34 9.28,30.34 9.18,30.24 8.98,30.24 8.88,30.34 8.69,30.34 8.59,30.24 8.39,30.24 8.29,30.34 8.1,30.34 8,30.24 7.81,30.24 7.7,30.34 7.51,30.34 7.41,30.24 7.22,30.24 7.11,30.34 6.92,30.34 6.82,30.24 6.63,30.24 6.53,30.34 6.16,30.34 6.07,30.25 6.07,29.66 5.98,29.58 5.86,29.58 5.78,29.66 5.78,30.25 5.69,30.34 5.57,30.34 5.48,30.25 5.48,29.66 5.39,29.58 5.27,29.58 5.19,29.66 5.19,30.25 5.1,30.34 4.79,30.34 4.44,29.99 4.44,29.34 4.52,29.25 5.49,29.25 5.58,29.17 5.58,29.05 5.49,28.96 4.52,28.96 4.44,28.87 4.44,28.75 4.52,28.66 5.49,28.66 5.58,28.58 5.58,28.46 5.49,28.37 4.52,28.37 4.44,28.28 4.44,28.16 4.52,28.07 5.49,28.07 5.58,27.99 5.58,27.87 5.49,27.78 4.52,27.78 4.44,27.69 4.44,26.78 4.75,26.47 4.75,25.78 v2(5.12,25.41)
  INT_L3 w0.094: v2(5.12,25.41) 4.73,25.02 4.73,14.61 v8(5.13,14.21)
  BOTTOM w0.114: v8(5.13,14.21) 5.22,14.11 R108.2
DDR2_A3: length 44.9
  TOP w0.114: U11.N2 v8(5.93,26.21)
  TOP w0.12: U10.N2 6.33,14.61 v8(5.93,15.01) ; v8(19.12,28.77) 19.14,28.79 19.63,28.79 20.02,29.17 U6.R27
  SIG_L5 w0.094: v8(19.12,28.77) 19.12,28.72 18.53,28.13 17.49,28.13 17.34,28.28 12.49,28.28 11.95,27.74 11.95,23.94 11.85,23.84 11.59,23.84 11.5,23.93 11.5,24.86 11.4,24.96 11.27,24.96 11.17,24.86 11.17,23.86 11.08,23.76 10.95,23.76 10.85,23.86 10.85,24.84 10.76,24.93 10.63,24.93 10.53,24.83 10.53,23.86 10.44,23.76 10.3,23.76 10.21,23.86 10.21,24.89 10.11,24.98 9.98,24.98 9.89,24.89 9.89,23.86 9.79,23.76 9.66,23.76 9.56,23.86 9.56,24.81 9.47,24.91 9.34,24.91 9.24,24.81 9.24,23.88 9.15,23.79 8.82,23.79 8.73,23.88 8.73,26.61 8.48,26.86 6.58,26.86 v8(5.93,26.21) 6.35,25.79 6.35,15.62 5.93,15.2 v8(5.93,15.01)
  BOTTOM w0.114: 5.93,16.4 5.91,16.42 R109.2
  BOTTOM w0.12: 5.93,16.4 6.19,16.14 6.19,15.27 v8(5.93,15.01)
DDR2_A4: length 44.8
  TOP w0.114: v8(5.13,20.61) 5.53,21.01 U11.P8 ; U10.P8 5.53,9.81 5.43,9.71
  TOP w0.12: v8(23.07,27.97) U6.P23 ; 5.43,9.71 v8(5.13,9.41) ; 5.53,21.01 v8(5.13,20.61)
  SIG_L5 w0.091: v8(5.13,9.41) U10.P8 5.53,12.56 4.75,13.34 4.75,19.66 5.13,20.03 v8(5.13,20.61)
  SIG_L8 w0.091: v8(23.07,27.97) 23.07,27.76 22.69,27.39 22.69,27.03 22.34,26.68 22.21,26.68 22.05,26.84 21.92,26.84 21.82,26.74 21.82,26.61 21.98,26.45 21.98,26.32 21.89,26.22 21.76,26.22 21.59,26.39 21.46,26.39 21.37,26.29 21.37,26.16 21.53,26 21.53,25.87 20.98,25.32 20.85,25.32 20.69,25.48 20.56,25.48 20.46,25.39 20.46,25.26 20.62,25.09 20.62,24.96 20.26,24.6 19.93,24.6 19.47,24.14 19.47,23.58 18.71,22.82 18.58,22.82 18.17,23.22 18.05,23.22 17.95,23.13 17.95,23 18.35,22.59 18.35,22.46 18.26,22.37 18.13,22.37 17.72,22.77 17.59,22.77 17.5,22.67 17.5,22.54 17.9,22.14 17.9,22.01 17.57,21.68 13.3,21.68 12.49,22.49 9.8,22.49 9.71,22.4 9.71,22.08 9.62,21.98 9.48,21.98 9.39,22.08 9.39,22.4 9.3,22.49 9.16,22.49 9.07,22.4 9.07,22.08 8.98,21.98 8.84,21.98 8.75,22.08 8.75,22.4 8.66,22.49 8.52,22.49 8.43,22.4 8.43,22.08 8.34,21.98 5.78,21.98 5.53,21.73 U11.P8 v8(5.13,20.61)
  BOTTOM w0.12: R110.2 5.53,8.03 5.53,9.01 v8(5.13,9.41)
DDR2_A5: length 44.5
  TOP w0.114: U10.P2 5.53,14.61 ; U11.P2 v8(5.13,26.21)
  TOP w0.12: 5.53,14.61 v8(5.13,15.01) ; v8(23.85,27.95) U6.P22
  SIG_L5 w0.094: v8(5.13,15.01) 5.13,15.21 5.55,15.63 5.55,23.66 5.13,24.09 v8(5.13,26.21) 5.13,26.46 5.86,27.19 5.86,27.86 6.03,28.03 7.72,28.03 7.81,28.12 7.81,28.85 7.91,28.94 18.14,28.94 18.49,29.3 19.22,29.3 19.44,29.08 19.57,29.08 19.73,29.24 19.86,29.24 19.96,29.14 19.96,29.01 19.8,28.85 19.8,28.72 20.11,28.41 20.37,28.41 20.46,28.5 20.46,29 20.56,29.1 20.69,29.1 20.79,29 20.79,28.5 20.88,28.41 21.01,28.41 21.11,28.5 21.11,29 21.2,29.1 21.34,29.1 21.43,29 21.43,28.5 21.52,28.41 21.66,28.41 21.75,28.5 21.75,29.36 21.85,29.45 21.98,29.45 22.08,29.36 22.08,28.5 22.17,28.41 22.3,28.41 22.4,28.5 22.4,29.31 22.49,29.4 22.63,29.4 22.72,29.31 22.72,28.5 22.82,28.41 22.95,28.41 23.04,28.5 23.04,29 23.14,29.1 23.27,29.1 23.37,29 23.37,28.5 23.46,28.41 23.75,28.41 23.85,28.32 v8(23.85,27.95)
  BOTTOM w0.114: 5.13,16.4 5.1,16.43 R111.2
  BOTTOM w0.12: 5.13,16.4 5.53,16 5.53,15.41 v8(5.13,15.01)
DDR2_A6: length 44.8
  TOP w0.114: U11.R8 4.73,21.01 ; U10.R8 4.73,9.81
  TOP w0.12: 4.73,21.01 v8(4.33,20.61) ; 4.73,9.81 v8(4.33,9.41) ; v8(21.47,27.97) U6.P25
  SIG_L5 w0.091: v8(4.33,20.61) 4.33,20.17 3.94,19.79 3.94,9.79 v8(4.33,9.41)
  SIG_L8 w0.091: v8(4.33,20.61) 4.74,21.02 4.74,22.47 5.1,22.82 5.57,22.82 5.66,22.73 5.66,22.53 5.75,22.44 5.89,22.44 5.98,22.53 5.98,22.73 6.07,22.82 6.21,22.82 6.3,22.73 6.3,22.53 6.39,22.44 6.53,22.44 6.62,22.53 6.62,22.73 6.71,22.82 6.85,22.82 6.94,22.73 6.94,22.53 7.03,22.44 7.17,22.44 7.26,22.53 7.26,22.73 7.35,22.82 7.49,22.82 7.58,22.73 7.58,22.53 7.67,22.44 7.81,22.44 7.9,22.53 7.9,22.73 8.02,22.85 16.81,22.85 17.26,23.3 17.26,25.36 18.74,26.84 18.98,26.84 19.07,26.74 19.07,26.01 19.16,25.92 19.3,25.92 19.39,26.01 19.39,26.74 19.48,26.84 19.62,26.84 19.71,26.74 19.71,26.01 19.8,25.92 19.94,25.92 20.03,26.01 20.03,26.74 20.12,26.84 20.26,26.84 20.35,26.74 20.35,26.01 20.44,25.92 20.58,25.92 20.67,26.01 20.67,26.74 20.76,26.84 21.28,26.84 21.47,27.03 v8(21.47,27.97)
  BOTTOM w0.12: v8(4.33,9.41) 4.73,9.01 4.73,8.02 R112.2
DDR2_A7: length 44.9
  TOP w0.114: U10.R2 4.63,14.71 ; U11.R2 v8(4.33,26.21)
  TOP w0.12: v8(25.47,27.17) U6.N20 ; 4.63,14.71 v8(4.33,15.01)
  SIG_L5 w0.094: v8(4.33,26.21) 4.33,22.19 4.72,21.8 4.72,20.19 4.33,19.79 v8(4.33,15.01)
  SIG_L8 w0.091: v8(4.33,26.21) 4.33,24.67 4.42,24.57 4.69,24.57 4.78,24.67 4.78,25.27 4.87,25.36 5.01,25.36 5.1,25.27 5.1,24.67 5.19,24.57 5.33,24.57 5.42,24.67 5.42,24.92 5.51,25.01 5.65,25.01 5.74,24.92 5.74,24.67 5.83,24.57 5.97,24.57 6.06,24.67 6.06,24.92 6.15,25.01 6.29,25.01 6.38,24.92 6.38,24.67 6.47,24.57 7.13,24.57 7.61,24.09 11.04,24.09 11.96,25.01 16.04,25.01 16.17,25.13 16.17,25.84 18.69,28.36 21.77,28.36 21.86,28.27 21.86,27.75 22.04,27.57 22.5,27.57 22.67,27.75 22.67,28.33 22.83,28.49 24.83,28.49 25.06,28.26 25.06,27.58 v8(25.47,27.17)
  BOTTOM w0.114: 4.33,16.4 4.3,16.43 R113.2
  BOTTOM w0.12: 4.33,16.4 4.51,16.22 4.51,15.19 v8(4.33,15.01)
DDR2_A8: length 44.9
  TOP w0.114: U11.T8 3.93,21.01 ; U10.T8 3.93,9.81
  TOP w0.12: v8(19.87,27.97) U6.P27 ; 3.93,21.01 v8(3.53,20.61) ; 3.93,9.81 v8(3.53,9.41)
  SIG_L5 w0.091: v8(3.53,20.61) 3.53,20.24 3.12,19.83 3.12,9.77 3.48,9.41 v8(3.53,9.41)
  SIG_L8 w0.091: v8(19.87,27.97) 19.42,27.52 18.38,27.52 16.53,25.67 16.53,24.32 16.32,24.12 15.08,24.12 14.6,24.6 12.01,24.6 11.12,23.71 6.65,23.71 6.56,23.8 6.56,24.15 6.47,24.24 6.33,24.24 6.24,24.15 6.24,23.8 6.15,23.71 6.01,23.71 5.92,23.8 5.92,24.15 5.83,24.24 5.69,24.24 5.6,24.15 5.6,23.8 5.51,23.71 5.37,23.71 5.28,23.8 5.28,24.15 5.19,24.24 5.05,24.24 4.96,24.15 4.96,23.8 4.87,23.71 4.73,23.71 4.64,23.8 4.64,24.15 4.55,24.24 3.29,24.24 3.14,24.09 3.14,23.84 3.23,23.75 3.74,23.75 3.83,23.66 3.83,23.52 3.74,23.43 3.23,23.43 3.14,23.34 3.14,23.2 3.23,23.11 3.74,23.11 3.83,23.02 3.83,22.88 3.74,22.79 3.23,22.79 3.14,22.7 3.14,22.56 3.23,22.47 3.74,22.47 3.83,22.38 3.83,22.24 3.74,22.15 3.23,22.15 3.14,22.06 3.14,20.99 v8(3.53,20.61)
  BOTTOM w0.12: v8(3.53,9.41) 3.93,9.01 3.93,8.01 R114.2
DDR2_A9: length 45
  TOP w0.114: 19.87,27.17 18.32,27.17 17.64,27.85 17.64,30.7 v2(17.59,30.75) ; 4.73,25.01 U11.R3 ; U10.R3 4.63,13.91
  TOP w0.12: 4.73,25.01 4.53,25.21 4.51,25.21 v2(4.31,25.41) ; 4.63,13.91 v8(4.33,14.21) ; 19.87,27.17 U6.N27
  INT_L3 w0.091: v2(4.31,25.41) 3.93,25.79 3.93,27.12 3.84,27.2 3.25,27.2 3.17,27.29 3.17,27.41 3.25,27.5 3.84,27.5 3.93,27.58 3.93,27.71 3.84,27.79 3.25,27.79 3.17,27.88 3.17,28 3.25,28.09 3.84,28.09 3.93,28.17 3.93,28.3 3.84,28.38 3.25,28.38 3.17,28.47 3.17,28.59 3.25,28.68 3.84,28.68 3.93,28.76 3.93,28.88 3.84,28.97 3.25,28.97 3.17,29.06 3.17,29.18 3.25,29.27 3.84,29.27 3.93,29.35 3.93,29.47 3.84,29.56 3.25,29.56 3.17,29.65 3.17,30.47 3.32,30.62 17.44,30.62 17.57,30.75 v2(17.59,30.75)
  INT_L3 w0.094: v8(4.33,14.21) 3.93,14.61 3.93,25.03 v2(4.31,25.41)
  BOTTOM w0.114: R115.2 4.44,14.1 v8(4.33,14.21)
DDR2_A10: length 44.8
  TOP w0.114: v8(7.53,10.21) 7.93,10.61 U10.L7 ; U11.L7 7.93,21.81
  TOP w0.12: 7.93,21.81 v8(7.53,21.41) ; v8(23.07,27.17) U6.N23
  SIG_L8 w0.091: v8(7.53,21.41) 7.92,21.02 8.87,21.02 8.96,20.93 8.96,20.32 9.06,20.23 9.19,20.23 9.28,20.32 9.28,20.95 9.38,21.04 9.51,21.04 9.6,20.95 9.6,20.32 9.7,20.23 9.83,20.23 9.92,20.32 9.92,20.93 10.02,21.02 10.15,21.02 10.24,20.93 10.24,20.32 10.34,20.23 10.47,20.23 10.56,20.32 10.56,20.93 10.66,21.02 11.16,21.02 11.28,21.14 11.28,22.07 11.37,22.16 11.5,22.16 11.6,22.07 11.6,21.14 11.69,21.04 11.82,21.04 11.92,21.14 11.92,22.07 12.01,22.16 12.14,22.16 12.24,22.07 12.24,21.14 12.33,21.04 18.46,21.04 18.77,21.35 18.77,21.48 18.43,21.82 18.43,21.95 18.52,22.05 18.65,22.05 18.99,21.71 19.12,21.71 19.22,21.81 19.22,21.94 18.88,22.28 18.88,22.41 18.98,22.5 19.11,22.5 19.45,22.16 19.58,22.16 19.67,22.26 19.67,22.39 19.33,22.73 19.33,22.86 19.43,22.96 19.56,22.96 19.9,22.62 20.03,22.62 20.26,22.85 20.26,24.12 23.07,26.93 v8(23.07,27.17)
  SIG_L10 w0.094: v8(7.53,21.41) 7.53,16.61 7.13,16.21 7.13,10.61 v8(7.53,10.21)
  BOTTOM w0.12: R116.2 7.53,10.96 v8(7.53,10.21)
DDR2_A11: length 44.9
  TOP w0.114: U10.R7 4.73,10.61 4.63,10.51 ; U11.R7 4.73,21.81
  TOP w0.12: 4.63,10.51 v8(4.33,10.21) ; v8(20.67,27.97) U6.P26 ; 4.73,21.81 v8(4.33,21.41)
  SIG_L8 w0.091: v8(4.33,21.41) 4.33,22.92 4.67,23.26 11.99,23.26 12.08,23.35 12.08,24.13 12.17,24.22 12.31,24.22 12.4,24.13 12.4,23.35 12.49,23.26 12.63,23.26 12.72,23.35 12.72,24.13 12.81,24.22 12.95,24.22 13.04,24.13 13.04,23.35 13.13,23.26 13.27,23.26 13.36,23.35 13.36,24.13 13.45,24.22 13.59,24.22 13.68,24.13 13.68,23.35 13.77,23.26 13.91,23.26 14,23.35 14,24.13 14.09,24.22 14.23,24.22 14.32,24.13 14.32,23.35 14.41,23.26 14.57,23.26 14.66,23.35 14.66,23.67 14.75,23.76 14.89,23.76 14.98,23.67 14.98,23.35 15.07,23.26 15.21,23.26 15.3,23.35 15.3,23.67 15.39,23.76 15.53,23.76 15.62,23.67 15.62,23.35 15.71,23.26 15.85,23.26 15.94,23.35 15.94,23.67 16.03,23.76 16.17,23.76 16.26,23.67 16.26,23.35 16.35,23.26 16.66,23.26 16.91,23.51 16.91,25.51 18.58,27.19 20.46,27.19 20.67,27.4 v8(20.67,27.97)
  SIG_L10 w0.094: v8(4.33,21.41) 3.93,21.01 3.93,13.81 4.38,13.36 4.38,10.26 v8(4.33,10.21)
  BOTTOM w0.12: R117.2 4.33,10.94 v8(4.33,10.21)
DDR2_A12: length 44.7
  TOP w0.114: U10.N7 6.33,10.61 6.23,10.51 ; v8(18.36,28.59) 18.36,28.1 18.89,27.57 U6.N28 ; U11.N7 6.33,21.81
  TOP w0.12: 6.23,10.51 v8(5.93,10.21) ; 6.33,21.81 v8(5.93,21.41)
  SIG_L5 w0.091: v8(5.93,21.41) 5.93,24.18 5.5,24.6 5.5,26.05 5.5,26.4 6.3,27.2 8.05,27.2 8.22,27.37 8.22,28.37 8.31,28.46 8.45,28.46 8.54,28.37 8.54,27.56 8.63,27.47 8.77,27.47 8.86,27.56 8.86,28.37 8.95,28.46 9.09,28.46 9.18,28.37 9.18,27.56 9.27,27.47 9.41,27.47 9.5,27.56 9.5,28.37 9.59,28.46 9.73,28.46 9.82,28.37 9.82,26.5 9.91,26.4 10.05,26.4 10.14,26.5 10.14,28.37 10.23,28.46 10.37,28.46 10.46,28.37 10.46,27.56 10.55,27.47 11.14,27.47 11.4,27.72 11.4,27.85 11.07,28.18 11.07,28.31 11.16,28.41 11.29,28.41 11.62,28.08 11.75,28.08 12.26,28.59 v8(18.36,28.59)
  SIG_L10 w0.094: v8(5.93,21.41) 5.53,21.01 5.53,13.81 5.98,13.36 5.98,10.26 v8(5.93,10.21)
  BOTTOM w0.12: R118.2 5.93,10.94 v8(5.93,10.21)
DDR2_A13: length 44.9
  TOP w0.114: U11.T3 3.93,25.01 ; U10.T3 3.93,13.81
  TOP w0.12: v8(23.87,30.37) U6.T22 ; 3.93,13.81 v8(3.53,14.21) ; 3.93,25.01 v8(3.53,25.41)
  INT_L3 w0.094: v8(3.53,14.21) 3.13,14.61 3.13,25.01 v8(3.53,25.41)
  SIG_L5 w0.094: v8(3.53,25.41) 3.93,25.81 3.93,27.38 3.83,27.47 3.51,27.47 3.42,27.57 3.42,27.7 3.51,27.8 5,27.8 5.1,27.89 5.1,28.03 5,28.12 4.12,28.12 4.03,28.21 4.03,28.35 4.12,28.44 4.83,28.44 4.92,28.54 4.92,29.27 5.3,29.65 6.17,29.65 6.26,29.75 6.26,29.81 6.36,29.91 6.49,29.91 6.59,29.81 6.59,29.75 6.68,29.65 6.81,29.65 6.91,29.75 6.91,29.81 7,29.91 7.14,29.91 7.23,29.81 7.23,29.75 7.33,29.65 7.46,29.65 7.55,29.75 7.55,29.81 7.65,29.91 7.78,29.91 7.88,29.81 7.88,29.75 7.97,29.65 8.11,29.65 8.2,29.75 8.2,29.81 8.29,29.91 8.43,29.91 8.52,29.81 8.52,29.75 8.62,29.65 8.75,29.65 8.84,29.75 8.84,29.81 8.94,29.91 9.07,29.91 9.17,29.81 9.17,29.75 9.26,29.65 9.4,29.65 9.49,29.75 9.49,29.81 9.58,29.91 9.72,29.91 9.81,29.81 9.81,29.75 9.91,29.65 10.04,29.65 10.14,29.75 10.14,29.81 10.23,29.91 10.36,29.91 10.46,29.81 10.46,29.75 10.55,29.65 10.69,29.65 10.78,29.75 10.78,29.81 10.87,29.91 11.01,29.91 11.1,29.81 11.1,29.75 11.2,29.65 11.33,29.65 11.43,29.75 11.43,29.81 11.52,29.91 11.65,29.91 11.75,29.81 11.75,29.75 11.84,29.65 11.98,29.65 12.07,29.75 12.07,29.81 12.16,29.91 12.3,29.91 12.39,29.81 12.39,29.75 12.49,29.65 12.62,29.65 12.72,29.75 12.72,29.81 12.81,29.91 12.94,29.91 13.04,29.81 13.04,29.75 13.13,29.65 13.27,29.65 13.36,29.75 13.36,29.81 13.53,29.99 13.96,29.99 14.06,29.88 14.28,29.88 14.38,29.99 18.08,29.99 18.86,30.77 20.01,30.77 20.39,30.39 21.45,30.39 21.89,29.96 23.45,29.96 v8(23.87,30.37)
  BOTTOM w0.114: v8(3.53,14.21) 3.65,14.09 R119.2
DDR2_A14: length 44.9
  TOP w0.114: U10.T7 3.93,10.61 ; U11.T7 3.93,21.81
  TOP w0.12: 3.93,10.61 v8(3.53,10.21) ; U6.R22 23.87,29.57 v8(23.87,29.57) ; 3.93,21.81 v8(3.53,21.41)
  SIG_L5 w0.091: v8(23.87,29.57) 24.27,29.98 24.27,30.66 24.16,30.77 20.46,30.77 20.13,31.1 18.53,31.1 17.8,30.37 5.61,30.37 2.98,27.74 2.98,27.41 2.51,26.94 2.51,25.78 3.24,22.11 v8(3.53,21.41)
  SIG_L10 w0.094: v8(3.53,10.21) 3.58,10.26 3.58,13.36 3.13,13.81 3.13,21.01 v8(3.53,21.41)
  BOTTOM w0.12: R120.2 3.53,10.92 v8(3.53,10.21)
DDR2_A15: length 44.9
  TOP w0.114: U10.M7 7.13,10.61 ; v8(6.73,21.41) 7.13,21.81 U11.M7
  TOP w0.12: v8(23.87,31.17) U6.U22 ; 7.13,10.61 v8(6.73,10.21) ; 7.13,21.81 v8(6.73,21.41)
  SIG_L5 w0.091: v8(6.73,21.41) 6.73,21.22 7.16,20.79 7.16,16.02 6.35,15.21 6.35,13.36 6.73,12.99 v8(6.73,10.21)
  SIG_L10 w0.091: v8(6.73,21.41) 5.53,22.61 5.53,23.1 5.44,23.19 5.34,23.19 5.25,23.28 5.25,23.46 5.34,23.56 5.44,23.56 5.53,23.65 5.53,23.83 5.44,23.92 5.34,23.92 5.25,24.01 5.25,24.2 5.34,24.29 5.44,24.29 5.53,24.38 5.53,24.56 5.44,24.65 5.34,24.65 5.25,24.74 5.25,24.93 5.34,25.02 5.44,25.02 5.53,25.11 5.53,27.78 8.09,30.34 15.61,30.34 15.92,30.65 15.92,32.12 16.58,32.78 18.1,32.78 18.51,32.37 22.67,32.37 v8(23.87,31.17)
  BOTTOM w0.12: R121.2 6.73,10.95 v8(6.73,10.21)
DDR2_BA0: length 44.9
  TOP w0.114: U10.M2 7.13,14.61 ; U11.M2 v8(6.73,26.21)
  TOP w0.12: 7.13,14.61 v8(6.73,15.01) ; v8(23.07,31.17) U6.U23
  SIG_L5 w0.094: v8(6.73,15.01) 7.46,15.74 7.46,20.85 7.15,21.16 7.15,25.79 v8(6.73,26.21)
  SIG_L10 w0.091: v8(6.73,26.21) 6.54,26.39 6.54,26.59 6.45,26.68 6.08,26.68 5.99,26.77 5.99,26.96 6.08,27.05 6.45,27.05 6.54,27.14 6.54,27.32 6.45,27.41 6.08,27.41 5.99,27.5 5.99,27.69 6.08,27.78 6.45,27.78 6.54,27.87 6.54,28.04 6.64,28.13 7.41,28.13 7.51,28.04 7.51,27.42 7.6,27.33 7.78,27.33 7.87,27.42 7.87,28.04 7.96,28.13 8.63,28.13 8.76,28.26 8.76,28.39 7.77,29.38 7.77,29.51 7.9,29.64 8.03,29.64 9.02,28.65 9.15,28.65 9.28,28.78 9.28,28.91 8.58,29.61 8.58,29.74 8.71,29.87 8.84,29.87 9.54,29.17 9.67,29.17 9.8,29.3 9.8,29.43 9.53,29.7 9.53,29.83 9.66,29.95 9.79,29.95 10.05,29.69 10.18,29.69 10.41,29.91 15.94,29.91 18.12,32.09 22.15,32.09 v8(23.07,31.17)
  BOTTOM w0.114: R122.2 6.75,16.42 6.73,16.4
  BOTTOM w0.12: 6.73,16.4 7.13,16 7.13,15.41 v8(6.73,15.01)
DDR2_BA1: length 44.8
  TOP w0.114: U11.N8 6.33,21.01 ; U10.N8 6.33,9.81
  TOP w0.12: v8(20.66,31.17) U6.U27 ; v8(5.93,9.41) 6.33,9.81 ; 6.33,21.01 v8(5.93,20.61)
  SIG_L5 w0.091: v8(5.93,20.61) 5.93,15.6 5.55,15.23 5.55,13.35 6.32,12.59 6.32,9.79 v8(5.93,9.41)
  SIG_L10 w0.091: v8(5.93,20.61) 6.34,21.02 6.9,21.02 7.15,21.27 7.15,21.56 7.61,22.02 7.61,22.51 7.52,22.61 6.41,22.61 6.32,22.7 6.32,22.88 6.41,22.97 7.52,22.97 7.61,23.06 7.61,23.25 7.52,23.34 6.41,23.34 6.32,23.43 6.32,23.61 6.41,23.7 7.52,23.7 7.61,23.79 7.61,23.98 7.52,24.07 6.41,24.07 6.32,24.16 6.32,24.34 6.41,24.43 7.52,24.43 7.61,24.53 7.61,24.68 7.94,25.01 7.94,26.86 10.53,29.45 15.92,29.45 18.25,31.79 19.91,31.79 20.53,31.17 v8(20.66,31.17)
  BOTTOM w0.12: R123.2 6.33,8.04 6.33,9.01 v8(5.93,9.41)
DDR2_BA2: length 44.5
  TOP w0.114: v2(20.68,30.38) U6.U26 ; U11.M3 6.73,25.41 v2(6.72,25.41) ; U10.M3 7.13,13.81
  TOP w0.12: 7.13,13.81 v8(6.73,14.21)
  INT_L3 w0.091: v2(6.72,25.41) 6.58,25.55 6.32,25.82 6.32,26.68 6.23,26.76 6.1,26.76 6.01,26.85 6.01,26.97 6.1,27.06 6.53,27.06 6.62,27.14 6.62,27.26 6.53,27.35 6.1,27.35 6.01,27.44 6.01,27.56 6.1,27.65 6.53,27.65 6.62,27.73 6.62,27.85 6.53,27.94 6.1,27.94 6.01,28.03 6.01,28.15 6.1,28.23 6.92,28.23 7,28.32 7,28.44 6.92,28.53 6.1,28.53 6.01,28.62 6.01,28.74 6.1,28.82 6.97,28.82 7.05,28.91 7.05,29.03 6.97,29.12 6.4,29.12 6.32,29.21 6.32,29.38 6.71,29.77 7.18,29.77 7.37,29.58 7.49,29.58 7.58,29.66 7.58,29.75 7.66,29.83 7.79,29.83 7.87,29.75 7.87,29.66 7.96,29.58 8.08,29.58 8.17,29.66 8.17,29.75 8.25,29.83 8.38,29.83 8.46,29.75 8.46,29.66 8.55,29.58 8.67,29.58 8.76,29.66 8.76,29.75 8.84,29.83 8.97,29.83 9.05,29.75 9.05,29.66 9.14,29.58 9.26,29.58 9.35,29.66 9.35,29.75 9.43,29.83 9.55,29.83 9.64,29.75 9.64,29.66 9.73,29.58 9.85,29.58 9.94,29.66 9.94,29.75 10.02,29.83 10.14,29.83 10.23,29.75 10.23,29.66 10.32,29.58 10.44,29.58 10.52,29.66 10.52,29.75 10.61,29.83 10.73,29.83 10.82,29.75 10.82,29.66 10.91,29.58 11.03,29.58 11.11,29.66 11.11,29.75 11.2,29.83 11.32,29.83 11.41,29.75 11.41,29.66 11.49,29.58 11.62,29.58 11.7,29.66 11.7,29.75 11.79,29.83 11.91,29.83 12,29.75 12,29.66 12.08,29.58 12.21,29.58 12.29,29.66 12.29,29.75 12.38,29.83 12.5,29.83 12.59,29.75 12.59,29.66 12.67,29.58 12.8,29.58 12.88,29.66 12.88,29.75 12.97,29.83 13.09,29.83 13.18,29.75 13.18,29.66 13.26,29.58 13.38,29.58 13.47,29.66 13.47,29.75 13.56,29.83 13.68,29.83 13.77,29.75 13.77,29.66 13.85,29.58 13.97,29.58 14.06,29.66 14.06,29.75 14.15,29.83 14.27,29.83 14.36,29.75 14.36,29.66 14.44,29.58 14.56,29.58 14.65,29.66 14.65,29.75 14.74,29.83 14.86,29.83 14.94,29.75 14.94,29.66 15.03,29.58 15.15,29.58 15.24,29.66 15.24,29.75 15.33,29.83 15.45,29.83 15.53,29.75 15.53,29.66 15.62,29.58 15.74,29.58 15.83,29.66 15.83,29.75 15.91,29.83 16.04,29.83 16.12,29.75 16.12,29.66 16.21,29.58 16.33,29.58 16.42,29.66 16.42,29.75 16.5,29.83 16.63,29.83 16.71,29.75 16.71,29.66 16.8,29.58 16.92,29.58 17.01,29.66 17.01,29.75 17.09,29.83 17.22,29.83 17.3,29.75 17.3,29.66 17.39,29.58 17.51,29.58 17.6,29.66 17.6,29.75 17.68,29.83 17.8,29.83 17.89,29.75 17.89,29.66 17.98,29.58 18.1,29.58 18.19,29.66 18.19,29.75 18.27,29.83 18.39,29.83 18.48,29.75 18.48,29.66 18.57,29.58 18.69,29.58 18.77,29.66 18.77,29.75 18.86,29.83 19.35,29.83 19.5,29.99 20.51,29.99 20.68,30.15 v2(20.68,30.38)
  INT_L3 w0.094: v8(6.73,14.21) 6.33,14.61 6.33,25.02 v2(6.72,25.41)
  BOTTOM w0.114: 6.73,13.9 6.73,13.77 R124.2
  BOTTOM w0.12: 6.73,13.9 v8(6.73,14.21)
DDR2_CASN: length 44.9
  TOP w0.114: U10.K3 8.63,13.91 ; U6.U28 19.06,31.18 16.88,31.18 16.48,30.77 16.48,29.07 v2(16.76,28.79) ; v2(8.32,25.41) 8.33,25.41 U11.K3
  TOP w0.12: 8.63,13.91 v8(8.33,14.21)
  INT_L3 w0.091: v2(8.32,25.41) 7.95,25.78 7.95,26.62 8.04,26.71 8.34,26.71 8.42,26.79 8.42,26.92 8.34,27 8.04,27 7.95,27.09 7.95,27.21 8.04,27.3 8.34,27.3 8.42,27.38 8.42,27.5 8.34,27.59 8.04,27.59 7.95,27.68 7.95,27.8 8.04,27.89 8.34,27.89 8.42,27.97 8.42,28.09 8.34,28.18 8.04,28.18 7.95,28.27 7.95,28.6 8.22,28.87 8.71,28.87 8.81,28.78 8.81,27.66 8.89,27.57 9.01,27.57 9.1,27.66 9.1,28.07 9.19,28.16 9.41,28.16 9.5,28.07 9.5,26.59 9.59,26.51 10.09,26.51 10.18,26.6 10.18,27.04 10.49,27.35 10.49,28.7 10.58,28.79 10.71,28.79 10.79,28.7 10.79,28.04 10.88,27.95 11,27.95 11.09,28.04 11.09,28.7 11.17,28.79 11.29,28.79 11.38,28.7 11.38,28.5 11.47,28.41 11.59,28.41 11.68,28.5 11.68,28.7 11.76,28.79 11.88,28.79 11.97,28.7 11.97,28.5 12.06,28.41 12.18,28.41 12.26,28.5 12.26,28.7 12.35,28.79 12.47,28.79 12.56,28.7 12.56,28.5 12.65,28.41 12.77,28.41 12.85,28.5 12.85,28.7 12.94,28.79 13.06,28.79 13.15,28.7 13.15,28.5 13.23,28.41 13.36,28.41 13.44,28.5 13.44,28.7 13.53,28.79 13.65,28.79 13.74,28.7 13.74,28.5 13.82,28.41 13.95,28.41 14.03,28.5 14.03,28.7 14.12,28.79 14.24,28.79 14.33,28.7 14.33,28.5 14.41,28.41 14.54,28.41 14.62,28.5 14.62,28.7 14.71,28.79 14.83,28.79 14.92,28.7 14.92,28.5 15,28.41 15.12,28.41 15.21,28.5 15.21,28.7 15.3,28.79 15.42,28.79 15.51,28.7 15.51,28.5 15.59,28.41 15.71,28.41 15.8,28.5 15.8,28.7 15.89,28.79 16.01,28.79 16.09,28.7 16.09,28.5 16.18,28.41 16.3,28.41 16.39,28.5 16.39,28.7 16.48,28.79 v2(16.76,28.79)
  INT_L3 w0.094: v2(8.32,25.41) 8.16,25.25 8.16,25.24 7.92,25 7.92,14.62 v8(8.33,14.21)
  BOTTOM w0.114: v8(8.33,14.21) 8.42,14.11 R104.2
DDR2_CKE: length 44.5
  TOP w0.114: U11.K9 8.63,20.11
  TOP w0.12: v8(22.27,31.17) U6.U24 ; 8.63,20.11 v8(8.33,19.81) ; U10.K9 v8(8.33,8.61)
  SIG_L10 w0.094: v8(8.33,8.61) 7.93,9.01 7.93,16.15 8.4,16.63 8.4,19.73 v8(8.33,19.81) 7.93,20.21 7.93,24.05 8.73,24.85 8.73,27.19 10.61,29.07 11.03,29.07 11.12,28.98 11.12,28.61 11.21,28.51 11.4,28.51 11.5,28.61 11.5,28.98 11.59,29.07 11.78,29.07 11.87,28.98 11.87,28.56 11.97,28.46 12.15,28.46 12.25,28.56 12.25,28.98 12.34,29.07 12.53,29.07 12.62,28.98 12.62,28.56 12.72,28.46 12.91,28.46 13,28.56 13,28.98 13.09,29.07 13.28,29.07 13.38,28.98 13.38,28.56 13.47,28.46 13.66,28.46 13.75,28.56 13.75,28.98 13.85,29.07 14.03,29.07 14.13,28.98 14.13,28.56 14.22,28.46 14.41,28.46 14.5,28.56 14.5,28.98 14.6,29.07 14.79,29.07 14.88,28.98 14.88,28.56 14.97,28.46 15.16,28.46 15.26,28.56 15.26,28.98 15.35,29.07 15.97,29.07 18.41,31.51 19.7,31.51 20.51,30.7 21.79,30.7 v8(22.27,31.17)
  BOTTOM w0.114: R101.2 R131.1
  BOTTOM w0.12: R101.2 8.33,7.88 v8(8.33,8.61)
DDR2_CLK_N: length 45
  TOP w0.102: U11.K7 8.73,21.81 v8(8.33,21.41) ; 8.63,10.51 U10.K7
  TOP w0.12: v8(8.33,10.21) 8.63,10.51 ; v8(19.87,30.37) U6.T27
  SIG_L10 w0.089: v8(19.87,30.37) 19.85,30.37 19.73,30.49 19.73,30.78 19.45,31.05 18.73,31.05 17.56,29.88 17.56,29.51 17.26,29.22 17.26,28.66 17.56,28.37 17.56,28.04 17.1,27.58 16.39,27.58 16.15,27.83 10.37,27.83 9.8,27.25 9.8,25.66 10.03,25.43 11.7,25.43 11.79,25.34 11.79,25.16 11.7,25.08 10.03,25.08 9.8,24.85 9.8,24.47 10.03,24.24 10.74,24.24 10.82,24.15 10.82,23.97 10.74,23.88 8.76,23.88 8.53,23.65 8.53,23.2 8.76,22.97 10.69,22.97 10.77,22.89 10.77,22.54 10.69,22.45 8.77,22.45 8.46,22.15 8.46,21.54 v8(8.33,21.41)
  SIG_L10 w0.094: v8(8.33,10.21) 8.61,10.49 8.61,12.62 9.52,13.53 9.52,20.04 8.62,20.93 8.62,21.08 8.33,21.37 v8(8.33,21.41)
  BOTTOM w0.102: R127.2 8.44,11.03
  BOTTOM w0.12: v8(8.33,10.21) 8.44,10.31 8.44,11.03
DDR2_CLK_P: length 45
  TOP w0.102: U10.J7 9.52,10.61
  TOP w0.12: v8(19.07,30.37) U6.T28 ; v8(9.13,10.21) 9.13,10.22 9.52,10.61 ; v8(9.13,21.41) 9.13,21.49 9.44,21.81 U11.J7
  SIG_L10 w0.089: 9.07,21.41 8.8,21.41 8.7,21.5 8.7,22.05 8.87,22.21 10.79,22.21 11.02,22.44 11.02,22.99 10.79,23.22 8.86,23.22 8.77,23.3 8.77,23.55 8.86,23.64 10.84,23.64 11.07,23.87 11.07,24.25 10.84,24.48 10.13,24.48 10.04,24.57 10.04,24.75 10.13,24.83 11.8,24.83 12.03,25.06 12.03,25.44 11.8,25.67 10.13,25.67 10.04,25.76 10.04,27.15 10.47,27.58 16.05,27.58 16.29,27.34 17.2,27.34 17.8,27.94 17.8,28.47 17.5,28.76 17.5,29.12 17.8,29.41 17.8,29.78 18.83,30.81 19.35,30.81 19.49,30.68 19.49,30.36 19.4,30.27 19.17,30.27 v8(19.07,30.37)
  SIG_L10 w0.094: v8(9.13,10.21) 8.86,10.48 8.86,12.52 9.76,13.42 9.76,20.14 8.86,21.04 8.86,21.2 9.07,21.41 v8(9.13,21.41)
  BOTTOM w0.12: R126.2 9.16,10.99 9.16,10.24 v8(9.13,10.21)
